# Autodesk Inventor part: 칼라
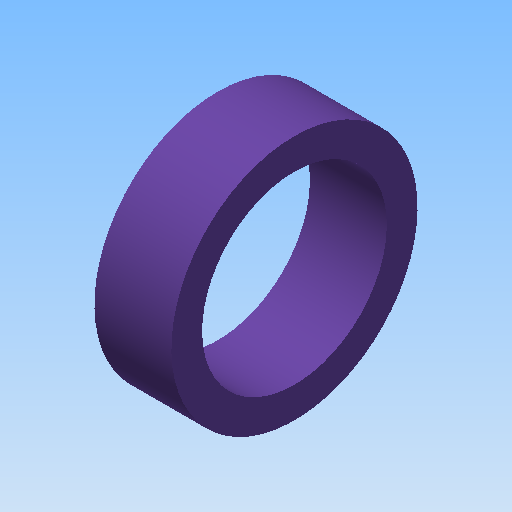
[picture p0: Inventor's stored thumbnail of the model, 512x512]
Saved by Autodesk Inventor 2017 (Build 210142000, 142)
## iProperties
Created: 2020-04
Part Number: 칼라
Material: 강철, 연강
Document SubType Name: Modeling
Designer: mduedu
Density: 7.86 g/cm^3
Mass: 3.45701 g
Surface Area: 6.15752 cm^2
Volume: 0.439823 cm^3
Appearance: 보라색
Author: mduedu
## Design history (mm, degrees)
sketch "스케치1"
  geometry: C1 r 8 at (0, 0); C2 r 6 at (0, 0); 1 further point
  constraints: 2 centre point, 2 coincident
  dimensions: "d0" = 16 diameter of C1; "d1" = 12 diameter of C2
extrude "돌출1" new body sketch "스케치1" distance "d2" = 5; taper "d3" = 0 deg
node "솔리드1"
